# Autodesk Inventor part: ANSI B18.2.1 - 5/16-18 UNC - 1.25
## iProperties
Comments: To add or edit properties for Autodesk Inventor files, use iProperties.
Created: 2005-06
Part Number: ANSI B18.2.1 - 5/16-18 UNC - 1.25
Vendor: Autodesk Inc.
Document SubType Name: Modeling
Designer: John Blackburn
Material: Default
Description: Hex Cap Screw
Standard: ANSI B18.2.1
Alert: To add or edit properties for Autodesk Inventor files, use iProperties.
Control State: 0
Master: False
Checked Out: False
Shininess: 64.0
Length Units: 11272
Angle Units: 11279
Time Units: 11290
Mass Units: 11286
Length Display Precision: 3
Angle Display Precision: 2
Compacted: True
EGR: 3
Classification: un/spsc 31161513
Density: 0.0
Volumn: 0.0
Area: 0.0
PropertySet Name: Model Information
Author: John Blackburn
Revision Number: 8
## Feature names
1. Body [Revolution]
2. Head [Extrusion]
3. Chamfer1 [Revolution]
4. Chamfer2
